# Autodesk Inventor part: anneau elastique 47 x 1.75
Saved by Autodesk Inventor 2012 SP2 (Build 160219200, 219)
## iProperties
Created: 2013-04
Part Number: anneau elastique 47 x 1.75
Material: Default
Document SubType Name: Modeling
Designer: papa
Density: 1 g/cm^3
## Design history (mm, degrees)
node "anneau elastique 47 x 1.751"
node "anneau elastique 47 x 1.75"
node "Base1"
